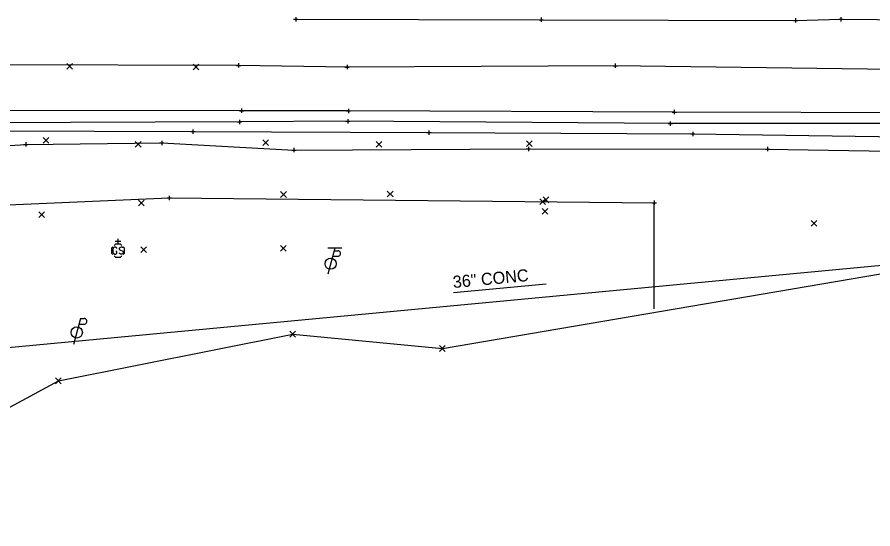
# Model space of a CAD drawing. Extents: x 146022 to 147632, y 437624 to 440659.
# Drawn here: x 147167.5 to 147365.2, y 438520.2 to 438638.5 of the extents above; entities that cross this region are included whole.
import ezdxf

# ---------------------------------------------------------------- set-up
doc = ezdxf.new("R2010")
doc.units = 0
for name, color, linetype in [('_CIVIL_CONSTRUCTION', 7, 'Continuous'), ('DR_P_Paved_Gutter', 7, 'Continuous'), ('DR_X_Storm_Sewer', 7, 'Continuous'), ('DR_X_Text', 7, 'Continuous'), ('DT_X_Contour_Major', 7, 'Continuous'), ('DT_X_Contour_Minor', 7, 'Continuous'), ('DT_X_Island', 7, 'Continuous'), ('PF_X_Ground_Line', 7, 'Continuous'), ('PV_P_Curb', 7, 'Continuous'), ('PV_P_Saw_Cut_Line', 7, 'Continuous'), ('RD_P_Anchor_Assembly', 7, 'Continuous'), ('RD_P_GR_Lt_Replaced', 7, 'Continuous'), ('SC_Scratch3', 7, 'Continuous'), ('SV_X_Terrain_Boundary', 7, 'Continuous')]:
    doc.layers.add(name, color=color, linetype=linetype)

msp = doc.modelspace()

# ---------------------------------------------------------------- linework, layer by layer
at = {"layer": '_CIVIL_CONSTRUCTION'}
for p, q in [((147178.94, 438626.45), (147180.27, 438627.79)), ((147178.94, 438627.79), (147180.27, 438626.45)), ((147208.14, 438626.29), (147209.47, 438627.62)), ((147208.14, 438627.62), (147209.47, 438626.29)), ((147173.45, 438609.34), (147174.78, 438610.68)), ((147173.45, 438610.68), (147174.78, 438609.34)), ((147194.76, 438608.41), (147196.1, 438609.74)), ((147194.76, 438609.74), (147196.1, 438608.41)), ((147224.24, 438608.79), (147225.58, 438610.13)), ((147224.24, 438610.13), (147225.58, 438608.79)), ((147250.44, 438608.42), (147251.77, 438609.76)), ((147250.44, 438609.76), (147251.77, 438608.42)), ((147285.17, 438608.57), (147286.5, 438609.9)), ((147285.17, 438609.9), (147286.5, 438608.57)), ((147228.37, 438596.83), (147229.7, 438598.17)), ((147228.37, 438598.17), (147229.7, 438596.83)), ((147253.01, 438596.96), (147254.34, 438598.3)), ((147253.01, 438598.3), (147254.34, 438596.96)), ((147195.53, 438594.9), (147196.86, 438596.23)), ((147195.53, 438596.23), (147196.86, 438594.9)), ((147288.26, 438595.2), (147289.6, 438596.53)), ((147288.26, 438596.53), (147289.6, 438595.2)), ((147289.04, 438595.6), (147290.37, 438596.94)), ((147289.04, 438596.94), (147290.37, 438595.6)), ((147288.78, 438592.93), (147290.11, 438594.27)), ((147288.78, 438594.27), (147290.11, 438592.93)), ((147172.48, 438592.19), (147173.81, 438593.53)), ((147172.48, 438593.53), (147173.81, 438592.19)), ((147350.94, 438590.19), (147352.27, 438591.53)), ((147350.94, 438591.53), (147352.27, 438590.19)), ((147196.06, 438584.08), (147197.4, 438585.42)), ((147196.06, 438585.42), (147197.4, 438584.08)), ((147228.3, 438584.41), (147229.63, 438585.75)), ((147228.3, 438585.75), (147229.63, 438584.41)), ((147230.49, 438564.54), (147231.82, 438565.88)), ((147230.49, 438565.88), (147231.82, 438564.54)), ((147265.09, 438561.24), (147266.42, 438562.58)), ((147265.09, 438562.58), (147266.42, 438561.24)), ((147176.35, 438553.78), (147177.68, 438555.12)), ((147176.35, 438555.12), (147177.68, 438553.78))]:
    msp.add_line(p, q, dxfattribs=at)
at = {"layer": 'DR_P_Paved_Gutter'}
msp.add_lwpolyline([(147090.74, 438611.98), (147096.12, 438612.12), (147118.78, 438612.16), (147162.43, 438612.19), (147208.09, 438612.03), (147262.63, 438611.82), (147323.61, 438611.5), (147382.66, 438610.66), (147430.09, 438609.36), (147432.84, 438608.99), (147438.6, 438606.61), (147442.2, 438603.35)], dxfattribs=at)
at = {"layer": 'DR_X_Storm_Sewer'}
msp.add_line((147070.7, 438553.26), (147483.94, 438592.14), dxfattribs=at)
msp.add_lwpolyline([(147092.74, 438591.99), (147202.64, 438596.73), (147314.7, 438595.59)], dxfattribs=at)
at = {"layer": 'DR_X_Text'}
msp.add_line((147289.76, 438576.78), (147268.33, 438574.77), dxfattribs=at)
at = {"layer": 'DT_X_Contour_Major'}
for p, q in [((147240.88, 438585.11), (147239.27, 438579.11)), ((147242.48, 438585.11), (147239.28, 438585.11)), ((147240.72, 438584.51), (147241.57, 438584.51)), ((147240.38, 438583.24), (147241.57, 438583.24))]:
    msp.add_line(p, q, dxfattribs=at)
msp.add_circle((147239.92, 438581.51), 1.3, dxfattribs=at)
msp.add_arc((147241.58, 438583.87), 0.638, 268.8767, 91.1233, dxfattribs=at)
at = {"layer": 'DT_X_Contour_Minor'}
for p, q in [((147182.11, 438568.83), (147180.51, 438562.83)), ((147182.11, 438568.83), (147182.96, 438568.83)), ((147181.77, 438567.55), (147182.96, 438567.55))]:
    msp.add_line(p, q, dxfattribs=at)
msp.add_circle((147181.26, 438565.63), 1.3, dxfattribs=at)
msp.add_arc((147182.97, 438568.19), 0.638, 268.8767, 91.1233, dxfattribs=at)
at = {"layer": 'DT_X_Island'}
for p, q in [((147191.43, 438586.64), (147190.16, 438586.64)), ((147190.79, 438586.01), (147190.79, 438587.28)), ((147190.79, 438584.53), (147190.79, 438584.53))]:
    msp.add_line(p, q, dxfattribs=at)
for points in [[(147191.69, 438585.7), (147191.39, 438586.01), (147190.2, 438586.01), (147189.9, 438585.71)], [(147189.62, 438585.42), (147189.31, 438585.12), (147189.31, 438583.94), (147189.61, 438583.63)], [(147190.54, 438585.01), (147190.52, 438585.07), (147190.49, 438585.14), (147190.42, 438585.2), (147190.33, 438585.28), (147190.27, 438585.3), (147190.22, 438585.31), (147190.15, 438585.33), (147189.99, 438585.33), (147189.93, 438585.31), (147189.89, 438585.3), (147189.84, 438585.28), (147189.74, 438585.2), (147189.68, 438585.11), (147189.64, 438585.01), (147189.62, 438584.87), (147189.59, 438584.67), (147189.59, 438584.41), (147189.6, 438584.19), (147189.65, 438584.03), (147189.73, 438583.88), (147189.79, 438583.83), (147189.87, 438583.78), (147190.01, 438583.73), (147190.15, 438583.73), (147190.28, 438583.75), (147190.33, 438583.78), (147190.38, 438583.8), (147190.44, 438583.85), (147190.49, 438583.93), (147190.54, 438584.04), (147190.54, 438584.36), (147190.27, 438584.36)], [(147191.93, 438585.21), (147191.91, 438585.24), (147191.87, 438585.26), (147191.76, 438585.3), (147191.62, 438585.33), (147191.52, 438585.33), (147191.48, 438585.33), (147191.32, 438585.29), (147191.18, 438585.21), (147191.09, 438585.11), (147191.07, 438585.01), (147191.07, 438584.94), (147191.09, 438584.84), (147191.19, 438584.75), (147191.88, 438584.37), (147191.95, 438584.32), (147191.97, 438584.27), (147192, 438584.19), (147192, 438584.12), (147191.98, 438584.04), (147191.97, 438583.99), (147191.95, 438583.93), (147191.92, 438583.88), (147191.9, 438583.84), (147191.86, 438583.8), (147191.82, 438583.78), (147191.77, 438583.75), (147191.73, 438583.74), (147191.62, 438583.73), (147191.44, 438583.73), (147191.33, 438583.75), (147191.17, 438583.84), (147191.07, 438583.92)], [(147191.97, 438583.63), (147192.27, 438583.94), (147192.27, 438585.12), (147191.97, 438585.42)], [(147189.89, 438583.35), (147190.2, 438583.05), (147191.39, 438583.05), (147191.69, 438583.35)]]:
    msp.add_lwpolyline(points, dxfattribs=at)
at = {"layer": 'PF_X_Ground_Line'}
msp.add_lwpolyline([(147090.56, 438608.28), (147100.12, 438605.93), (147134.16, 438606.88), (147169.46, 438609.09), (147200.89, 438609.42), (147231.43, 438607.76), (147285.62, 438608.05), (147340.88, 438607.99), (147430.19, 438606.52), (147440.56, 438602.17), (147446.94, 438588.76), (147447.8, 438583.92), (147447.86, 438583.13)], dxfattribs=at)
at = {"layer": 'PV_P_Curb'}
msp.add_line((147218.64, 438627.35), (147144.83, 438627.48), dxfattribs=at)
msp.add_lwpolyline([(147443.52, 438625.99), (147375.64, 438626.29), (147305.7, 438627.27), (147243.72, 438626.94), (147218.64, 438627.35)], dxfattribs=at)
at = {"layer": 'PV_P_Saw_Cut_Line'}
msp.add_line((147314.71, 438571.05), (147314.7, 438595.59), dxfattribs=at)
at = {"layer": 'RD_P_Anchor_Assembly'}
for p, q in [((147231.36, 438637.99), (147232.36, 438637.99)), ((147231.86, 438638.49), (147231.86, 438637.49)), ((147231.86, 438637.99), (147231.86, 438637.99)), ((147288.09, 438637.9), (147289.09, 438637.9)), ((147288.59, 438638.4), (147288.59, 438637.4)), ((147288.59, 438637.9), (147288.59, 438637.9)), ((147346.86, 438637.73), (147347.86, 438637.73)), ((147347.36, 438638.23), (147347.36, 438637.23)), ((147347.36, 438637.73), (147347.36, 438637.73)), ((147357.35, 438637.99), (147358.35, 438637.99)), ((147357.85, 438638.49), (147357.85, 438637.49)), ((147357.85, 438637.99), (147357.85, 438637.99)), ((147218.64, 438627.85), (147218.64, 438626.85)), ((147305.7, 438627.77), (147305.7, 438626.77)), ((147218.14, 438627.35), (147219.14, 438627.35)), ((147218.64, 438627.35), (147218.64, 438627.35)), ((147243.22, 438626.94), (147244.22, 438626.94)), ((147243.72, 438627.44), (147243.72, 438626.44)), ((147243.72, 438626.94), (147243.72, 438626.94)), ((147305.2, 438627.27), (147306.2, 438627.27)), ((147305.7, 438627.27), (147305.7, 438627.27)), ((147218.86, 438616.86), (147219.86, 438616.86)), ((147219.36, 438617.36), (147219.36, 438616.36)), ((147219.36, 438616.86), (147219.36, 438616.86)), ((147243.55, 438616.81), (147244.55, 438616.81)), ((147244.05, 438617.31), (147244.05, 438616.31)), ((147244.05, 438616.81), (147244.05, 438616.81)), ((147318.83, 438616.54), (147319.83, 438616.54)), ((147319.33, 438617.04), (147319.33, 438616.04)), ((147319.33, 438616.54), (147319.33, 438616.54)), ((147218.35, 438614.27), (147219.35, 438614.27)), ((147218.85, 438614.77), (147218.85, 438613.77)), ((147218.85, 438614.27), (147218.85, 438614.27)), ((147243.37, 438614.42), (147244.37, 438614.42)), ((147243.87, 438614.92), (147243.87, 438613.92)), ((147243.87, 438614.42), (147243.87, 438614.42)), ((147317.89, 438613.89), (147318.89, 438613.89)), ((147318.39, 438614.39), (147318.39, 438613.39)), ((147318.39, 438613.89), (147318.39, 438613.89)), ((147207.59, 438612.03), (147208.59, 438612.03)), ((147208.09, 438612.53), (147208.09, 438611.53)), ((147208.09, 438612.03), (147208.09, 438612.03)), ((147262.13, 438611.82), (147263.13, 438611.82)), ((147262.63, 438612.32), (147262.63, 438611.32)), ((147262.63, 438611.82), (147262.63, 438611.82)), ((147323.61, 438612), (147323.61, 438611)), ((147200.89, 438609.92), (147200.89, 438608.92)), ((147323.11, 438611.5), (147324.11, 438611.5)), ((147323.61, 438611.5), (147323.61, 438611.5)), ((147168.96, 438609.09), (147169.96, 438609.09)), ((147169.46, 438609.59), (147169.46, 438608.59)), ((147169.46, 438609.09), (147169.46, 438609.09)), ((147200.39, 438609.42), (147201.39, 438609.42)), ((147200.89, 438609.42), (147200.89, 438609.42)), ((147230.93, 438607.76), (147231.93, 438607.76)), ((147231.43, 438608.26), (147231.43, 438607.26)), ((147231.43, 438607.76), (147231.43, 438607.76)), ((147285.12, 438608.05), (147286.12, 438608.05)), ((147285.62, 438608.55), (147285.62, 438607.55)), ((147285.62, 438608.05), (147285.62, 438608.05)), ((147340.38, 438607.99), (147341.38, 438607.99)), ((147340.88, 438608.49), (147340.88, 438607.49)), ((147340.88, 438607.99), (147340.88, 438607.99)), ((147202.14, 438596.73), (147203.14, 438596.73)), ((147202.64, 438597.23), (147202.64, 438596.23)), ((147202.64, 438596.73), (147202.64, 438596.73)), ((147314.7, 438596.09), (147314.7, 438595.09)), ((147314.2, 438595.59), (147315.2, 438595.59)), ((147314.7, 438595.59), (147314.7, 438595.59))]:
    msp.add_line(p, q, dxfattribs=at)
at = {"layer": 'RD_P_GR_Lt_Replaced'}
msp.add_lwpolyline([(147441.08, 438612.46), (147376.87, 438613.91), (147318.39, 438613.89), (147243.87, 438614.42), (147218.85, 438614.27), (147160.23, 438614.06), (147116.28, 438615.1), (147116.37, 438616.32), (147097.65, 438616.22), (147092.09, 438613.53), (147091.95, 438613.68)], dxfattribs=at)
at = {"layer": 'SC_Scratch3'}
for points in [[(147231.86, 438637.99), (147288.59, 438637.9), (147347.36, 438637.73), (147357.85, 438637.99), (147408.76, 438637.55), (147442.63, 438637.34)], [(147441.54, 438616), (147377.93, 438616.36), (147319.33, 438616.54), (147244.05, 438616.81), (147219.36, 438616.86), (147159.11, 438616.91), (147088.59, 438616.85)]]:
    msp.add_lwpolyline(points, dxfattribs=at)
at = {"layer": 'SV_X_Terrain_Boundary'}
msp.add_lwpolyline([(147113.81, 438520.22), (147177.01, 438554.45), (147231.16, 438565.21), (147265.76, 438561.91), (147390.47, 438583.18), (147427.48, 438581.67), (147447.86, 438583.13), (147451.41, 438585.81), (147462.29, 438588.25), (147470.97, 438613.92), (147441.54, 438616), (147443.52, 438625.99), (147442.63, 438637.34), (147442.47, 438641.05), (147440.21, 438644.72), (147444.24, 438659.07), (147444.23, 438674.06), (147411.94, 438681.71), (147340.71, 438676.77), (147269.57, 438686.84), (147201.59, 438744.19), (147187.75, 438754.72), (147168.32, 438765.47), (147156.85, 438763.96)], dxfattribs=at)

# ---------------------------------------------------------------- texts
at = {"layer": 'DR_X_Text'}
msp.add_text('36" CONC', height=2.8, rotation=5.3754, dxfattribs=at).set_placement((147268.29, 438575.87))

doc.saveas('drawing.dxf')
